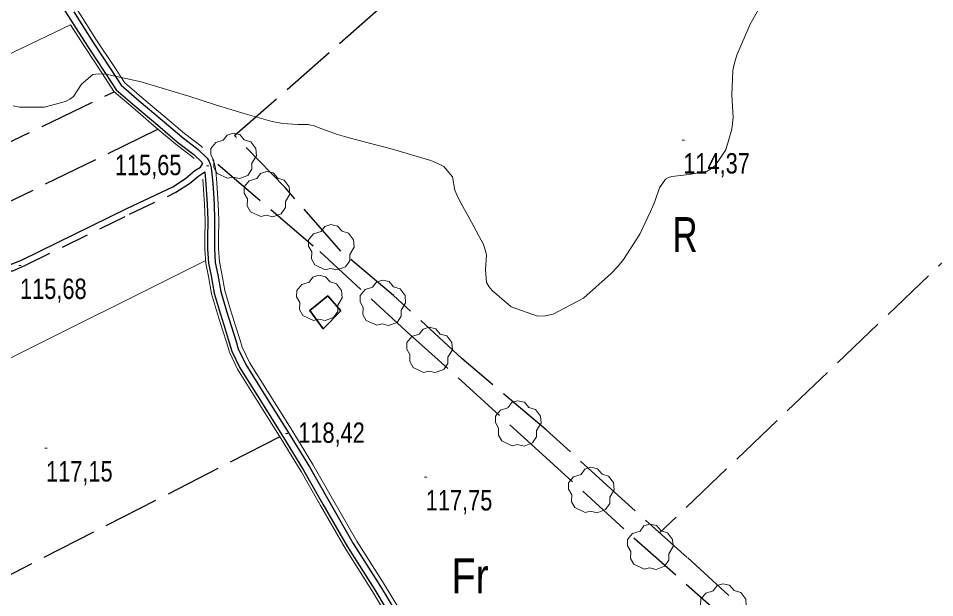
# Model space of a CAD drawing. Extents: x 487425 to 492029, y 4383576 to 4386788.
# Drawn here: x 489030 to 489424, y 4385743 to 4385991.9 of the extents above; entities that cross this region are included whole.
import ezdxf
from ezdxf.enums import TextEntityAlignment as Align

# ---------------------------------------------------------------- set-up
doc = ezdxf.new("R2010")
doc.units = 0
doc.header["$LTSCALE"] = 4
doc.linetypes.add('LONG_DASHED', pattern=[7.5, 6, -1.5])
doc.linetypes.add('MEDIUM_DASHED', pattern=[4.5, 3, -1.5])
for name, color, linetype, lineweight in [('25', 7, 'LONG_DASHED', 25), ('29', 7, 'Continuous', 13), ('38', 7, 'Continuous', 25), ('47', 7, 'Continuous', 35), ('51', 7, 'Continuous', 13), ('7', 7, 'Continuous', 13), ('9', 7, 'Continuous', 13)]:
    doc.layers.add(name, color=color, linetype=linetype, lineweight=lineweight)
doc.layers.add('31', color=7, linetype='Continuous')

msp = doc.modelspace()

# ---------------------------------------------------------------- linework, layer by layer
at = {"layer": '25'}
for p, q in [((488823.7, 4385841.92), (489071.21, 4385960.37)), ((489486.39, 4385943.41), (489305.75, 4385770.85))]:
    msp.add_line(p, q, dxfattribs=at)
for points in [[(489440.72, 4385647.8), (489419.55, 4385666.12), (489411.02, 4385668.4), (489411.06, 4385671.92), (489385.11, 4385699.07), (489357.64, 4385723.62), (489317.54, 4385760.31), (489289.47, 4385785.39), (489257.02, 4385815.16), (489220.69, 4385845.74), (489191.36, 4385872.85), (489168.69, 4385891.87), (489144.7, 4385919.22), (489122.97, 4385941.6), (489239.75, 4386043.95), (489321.93, 4386119.99), (489486.42, 4385943.37)], [(489090.11, 4385944.28), (488961.59, 4385881.69), (488988.3, 4385826.93)], [(489115.71, 4385929.31), (489159.69, 4385891.74), (489196.81, 4385857.49), (489250.5, 4385809.01), (489294.68, 4385768.67), (489335.01, 4385733.1), (489368.49, 4385701.89), (489404.14, 4385669.9), (489456.29, 4385624.52), (489481.26, 4385603.45)], [(489142.46, 4385812.11), (488991.66, 4385734.98), (489035.67, 4385658.64)]]:
    msp.add_lwpolyline(points, dxfattribs=at)
at = {"layer": '29'}
for points in [[(489119.97, 4385923.19), (489115.43, 4385925.31), (489114.02, 4385927.85), (489114.12, 4385930.83), (489112.75, 4385933.24), (489112.79, 4385935.99), (489114.95, 4385938.59), (489118.14, 4385939.59), (489119.79, 4385941.78), (489122.36, 4385942.61), (489125.22, 4385941.96), (489127.17, 4385939.69), (489129.98, 4385938.87), (489132.11, 4385936.02), (489132.35, 4385932.89), (489130.47, 4385929.74), (489130.47, 4385927.06), (489128.65, 4385924.45), (489125.03, 4385923.11), (489122.26, 4385923.74)], [(489134.33, 4385906.74), (489129.79, 4385908.86), (489128.38, 4385911.4), (489128.48, 4385914.38), (489127.11, 4385916.79), (489127.15, 4385919.54), (489129.31, 4385922.14), (489132.5, 4385923.14), (489134.15, 4385925.33), (489136.72, 4385926.16), (489139.58, 4385925.51), (489141.53, 4385923.24), (489144.34, 4385922.42), (489146.47, 4385919.57), (489146.71, 4385916.44), (489144.83, 4385913.29), (489144.83, 4385910.61), (489143.01, 4385908), (489139.39, 4385906.66), (489136.62, 4385907.29)], [(489161.98, 4385883.92), (489157.44, 4385886.04), (489156.03, 4385888.58), (489156.13, 4385891.56), (489154.76, 4385893.97), (489154.8, 4385896.72), (489156.96, 4385899.32), (489160.15, 4385900.32), (489161.8, 4385902.51), (489164.37, 4385903.34), (489167.23, 4385902.69), (489169.18, 4385900.42), (489171.99, 4385899.6), (489174.12, 4385896.75), (489174.36, 4385893.62), (489172.48, 4385890.47), (489172.48, 4385887.79), (489170.66, 4385885.18), (489167.04, 4385883.84), (489164.27, 4385884.47)], [(489156.86, 4385862.15), (489152.32, 4385864.27), (489150.91, 4385866.81), (489151.01, 4385869.79), (489149.64, 4385872.2), (489149.68, 4385874.95), (489151.84, 4385877.55), (489155.03, 4385878.55), (489156.68, 4385880.74), (489159.25, 4385881.57), (489162.11, 4385880.92), (489164.06, 4385878.65), (489166.87, 4385877.83), (489169, 4385874.98), (489169.24, 4385871.85), (489167.36, 4385868.7), (489167.36, 4385866.02), (489165.54, 4385863.41), (489161.92, 4385862.07), (489159.15, 4385862.7)], [(489184.14, 4385860.04), (489179.6, 4385862.16), (489178.19, 4385864.7), (489178.29, 4385867.68), (489176.92, 4385870.09), (489176.96, 4385872.84), (489179.12, 4385875.44), (489182.31, 4385876.44), (489183.96, 4385878.63), (489186.53, 4385879.46), (489189.39, 4385878.81), (489191.34, 4385876.54), (489194.15, 4385875.72), (489196.28, 4385872.87), (489196.52, 4385869.74), (489194.64, 4385866.59), (489194.64, 4385863.91), (489192.82, 4385861.3), (489189.2, 4385859.96), (489186.43, 4385860.59)], [(489204.24, 4385839.78), (489199.7, 4385841.9), (489198.29, 4385844.44), (489198.39, 4385847.42), (489197.02, 4385849.83), (489197.06, 4385852.58), (489199.22, 4385855.18), (489202.41, 4385856.18), (489204.06, 4385858.37), (489206.63, 4385859.2), (489209.49, 4385858.55), (489211.44, 4385856.28), (489214.25, 4385855.46), (489216.38, 4385852.61), (489216.62, 4385849.48), (489214.74, 4385846.33), (489214.74, 4385843.65), (489212.92, 4385841.04), (489209.3, 4385839.7), (489206.53, 4385840.33)], [(489242.37, 4385808.21), (489237.83, 4385810.33), (489236.42, 4385812.87), (489236.52, 4385815.85), (489235.15, 4385818.26), (489235.19, 4385821.01), (489237.35, 4385823.61), (489240.54, 4385824.61), (489242.19, 4385826.8), (489244.76, 4385827.63), (489247.62, 4385826.98), (489249.57, 4385824.71), (489252.38, 4385823.89), (489254.51, 4385821.04), (489254.75, 4385817.91), (489252.87, 4385814.76), (489252.87, 4385812.08), (489251.05, 4385809.47), (489247.43, 4385808.13), (489244.66, 4385808.76)], [(489273.78, 4385779.57), (489269.24, 4385781.69), (489267.83, 4385784.23), (489267.93, 4385787.21), (489266.56, 4385789.62), (489266.6, 4385792.37), (489268.76, 4385794.97), (489271.95, 4385795.97), (489273.6, 4385798.16), (489276.17, 4385798.99), (489279.03, 4385798.34), (489280.98, 4385796.07), (489283.79, 4385795.25), (489285.92, 4385792.4), (489286.16, 4385789.27), (489284.28, 4385786.12), (489284.28, 4385783.44), (489282.46, 4385780.83), (489278.84, 4385779.49), (489276.07, 4385780.12)], [(489299.16, 4385755.2), (489294.62, 4385757.32), (489293.21, 4385759.86), (489293.31, 4385762.84), (489291.94, 4385765.25), (489291.98, 4385768), (489294.14, 4385770.6), (489297.33, 4385771.6), (489298.98, 4385773.79), (489301.55, 4385774.62), (489304.41, 4385773.97), (489306.36, 4385771.7), (489309.17, 4385770.88), (489311.3, 4385768.03), (489311.54, 4385764.9), (489309.66, 4385761.75), (489309.66, 4385759.07), (489307.84, 4385756.46), (489304.22, 4385755.12), (489301.45, 4385755.75)], [(489330.6, 4385729.56), (489326.06, 4385731.68), (489324.65, 4385734.22), (489324.75, 4385737.2), (489323.38, 4385739.61), (489323.42, 4385742.36), (489325.58, 4385744.96), (489328.77, 4385745.96), (489330.42, 4385748.15), (489332.99, 4385748.98), (489335.85, 4385748.33), (489337.8, 4385746.06), (489340.61, 4385745.24), (489342.74, 4385742.39), (489342.98, 4385739.26), (489341.1, 4385736.11), (489341.1, 4385733.43), (489339.28, 4385730.82), (489335.66, 4385729.48), (489332.89, 4385730.11)]]:
    msp.add_lwpolyline(points, close=True, dxfattribs=at)
at = {"layer": '38'}
for points in [[(489042.28, 4386007.28), (489051.34, 4385993.15), (489059.68, 4385979.99), (489067.21, 4385968.71), (489072.01, 4385961.22), (489080.11, 4385954.34), (489089.92, 4385945.97), (489098.43, 4385938.79), (489105.44, 4385933.43), (489108.86, 4385930.08), (489109.24, 4385929.38)], [(489053.8, 4385994.72), (489062.13, 4385981.58), (489069.65, 4385970.31), (489074.23, 4385963.16), (489082, 4385956.56), (489091.81, 4385948.19), (489100.26, 4385941.07), (489107.36, 4385935.63), (489111.19, 4385931.87), (489112.03, 4385930.4), (489112.57, 4385928.8), (489112.88, 4385927.75), (489113.11, 4385926.38), (489113.57, 4385920.93), (489114.15, 4385912.19), (489114.37, 4385905.26), (489114.28, 4385897.37), (489114.31, 4385892.98), (489114.69, 4385887.06), (489115.74, 4385881.77), (489117.07, 4385874.52), (489119.51, 4385866.14), (489121.68, 4385859.3), (489123.49, 4385853.49), (489124.56, 4385849.94), (489127.8, 4385843.18), (489136.26, 4385829.62), (489146.5, 4385813.37), (489155.13, 4385799.23), (489163.51, 4385784.57), (489174.02, 4385766.31), (489185.74, 4385747.81), (489194.72, 4385732.92)], [(489016.31, 4385888.36), (489019.94, 4385886.53), (489023.86, 4385886.14), (489027.04, 4385886.24), (489031.64, 4385888.19), (489076.59, 4385910.25), (489096.45, 4385919.6), (489101.91, 4385923.13), (489105.94, 4385926.55), (489108.3, 4385928.01), (489109.24, 4385929.38)], [(489110.22, 4385925.95), (489110.66, 4385920.71), (489111.24, 4385912.05), (489111.46, 4385905.23), (489111.37, 4385897.37), (489111.4, 4385892.88), (489111.79, 4385886.68), (489112.87, 4385881.22), (489114.23, 4385873.84), (489116.73, 4385865.29), (489118.9, 4385858.42), (489120.71, 4385852.64), (489121.84, 4385848.89), (489125.24, 4385841.78), (489133.79, 4385828.08), (489144.02, 4385811.83), (489152.62, 4385797.75), (489160.99, 4385783.12), (489171.53, 4385764.8), (489183.26, 4385746.28), (489192.23, 4385731.42), (489204.59, 4385710.88), (489224.39, 4385677.11), (489231.34, 4385665.63)]]:
    msp.add_lwpolyline(points, dxfattribs=at)
at = {"layer": '38', "linetype": 'MEDIUM_DASHED'}
msp.add_lwpolyline([(489015.07, 4385885.9), (489019.16, 4385883.84), (489023.76, 4385883.38), (489027.64, 4385883.5), (489032.79, 4385885.68), (489077.79, 4385907.76), (489097.79, 4385917.19), (489103.56, 4385920.91), (489107.57, 4385924.31), (489110.22, 4385925.95)], dxfattribs=at)
at = {"layer": '47'}
msp.add_lwpolyline([(489168.63, 4385866.28), (489161.11, 4385858.49), (489155.28, 4385866.44), (489163.07, 4385872.65)], close=True, dxfattribs=at)
at = {"layer": '51'}
for p, q in [((488805.88, 4385871.46), (489052.49, 4385989.15)), ((489110.55, 4385887.85), (488868.95, 4385767.45))]:
    msp.add_line(p, q, dxfattribs=at)
for points in [[(489046.25, 4386009.83), (489055.33, 4385995.7), (489063.65, 4385982.57), (489071.17, 4385971.3), (489075.61, 4385964.36), (489083.17, 4385957.94), (489092.98, 4385949.58), (489101.4, 4385942.49), (489108.55, 4385937), (489109.2, 4385936.38)], [(489105.59, 4385931.65), (489104.67, 4385932.54), (489097.69, 4385937.87), (489089.16, 4385945.07), (489079.35, 4385953.45), (489071.12, 4385960.44), (489066.23, 4385968.07), (489058.7, 4385979.35), (489052.49, 4385989.15)], [(489196.27, 4385733.85), (489187.28, 4385748.77), (489175.57, 4385767.25), (489165.09, 4385785.48), (489156.69, 4385800.15), (489148.04, 4385814.33), (489137.8, 4385830.58), (489129.39, 4385844.06), (489126.25, 4385850.6), (489125.23, 4385854.02), (489123.41, 4385859.85), (489121.25, 4385866.66), (489118.83, 4385874.93), (489117.52, 4385882.11), (489116.49, 4385887.29), (489116.13, 4385893.05), (489116.1, 4385897.36), (489116.19, 4385905.28), (489115.96, 4385912.28), (489115.38, 4385921.07), (489114.91, 4385926.61), (489114.65, 4385928.16), (489114.3, 4385929.35), (489113.69, 4385931.14), (489113.56, 4385931.39)], [(489229.57, 4385666.3), (489223.38, 4385676.51), (489203.58, 4385710.28), (489191.22, 4385730.81), (489182.26, 4385745.66), (489170.52, 4385764.19), (489159.97, 4385782.54), (489151.61, 4385797.15), (489143.02, 4385811.21), (489132.79, 4385827.46), (489124.21, 4385841.21), (489120.74, 4385848.46), (489119.59, 4385852.3), (489117.78, 4385858.07), (489115.61, 4385864.95), (489113.09, 4385873.57), (489111.72, 4385881), (489110.62, 4385886.53), (489110.23, 4385892.84), (489110.2, 4385897.37), (489110.29, 4385905.22), (489110.07, 4385911.99), (489109.49, 4385920.62), (489109.31, 4385922.77)]]:
    msp.add_lwpolyline(points, dxfattribs=at)
at = {"layer": '7'}
for p, q in [((489315.41, 4385939.63), (489316.41, 4385939.63)), ((489110.84, 4385928.53), (489111.84, 4385928.53)), ((489030.23, 4385885.71), (489031.23, 4385885.71)), ((489144.87, 4385813.51), (489145.87, 4385813.51)), ((489041.42, 4385807.26), (489042.42, 4385807.26)), ((489204.68, 4385794.82), (489205.68, 4385794.82))]:
    msp.add_line(p, q, dxfattribs=at)
at = {"layer": '9'}
for points in [[(489053.76, 4385958.29), (489057.16, 4385963.7), (489062.03, 4385967.74), (489064.56, 4385968.03), (489067.6, 4385967.96), (489082.85, 4385964.71), (489097.96, 4385960.14), (489100.93, 4385959.23), (489103.36, 4385958.48), (489107.72, 4385957.08), (489111.15, 4385955.93), (489113, 4385955.34), (489115.24, 4385954.64), (489126.54, 4385951.13), (489138.58, 4385947.79), (489141.28, 4385947.19), (489143.7, 4385946.73), (489150.16, 4385946.26), (489154.57, 4385946.26), (489155.71, 4385946.1), (489156.81, 4385945.88), (489160.45, 4385944.48), (489167.19, 4385942.02), (489170.24, 4385941.12), (489173.8, 4385940.13), (489190.92, 4385935.76), (489207.32, 4385930.88), (489210.42, 4385929.57), (489212.9, 4385928.28), (489216.65, 4385923.76), (489217.72, 4385918.11), (489218.51, 4385916.1), (489219.51, 4385913.9), (489224.91, 4385904.36), (489229.96, 4385894.68), (489230.74, 4385892.39), (489231.25, 4385890.27), (489230.88, 4385884.03), (489231.28, 4385878.43), (489232.29, 4385876.72), (489233.68, 4385874.94), (489241.94, 4385867.93), (489253.26, 4385863.97), (489256.59, 4385864.12), (489260, 4385864.8), (489273.01, 4385871.75), (489284.97, 4385882.32), (489287.73, 4385885.28), (489290.23, 4385888.26), (489297.26, 4385899.16), (489301.85, 4385908.91), (489302.83, 4385911.17), (489303.67, 4385913.24), (489305.64, 4385919.11), (489308.29, 4385922.79), (489309.56, 4385923.48), (489311.06, 4385924.02), (489318.4, 4385924.79), (489326.22, 4385926.32), (489328.01, 4385927.35), (489329.65, 4385928.64), (489334.21, 4385935.49), (489336.76, 4385944.29), (489337.12, 4385946.81), (489337.33, 4385949.37), (489336.86, 4385958.91), (489337.18, 4385969.53), (489337.89, 4385972.77), (489338.88, 4385976.14), (489344.7, 4385989.38), (489351.24, 4386001.18)], [(489027.82, 4385954.29), (489030.53, 4385953.79), (489041.05, 4385953.78), (489050.26, 4385956.14), (489052.15, 4385957.14), (489053.76, 4385958.29)]]:
    msp.add_lwpolyline(points, dxfattribs=at)

# ---------------------------------------------------------------- texts
at = {"layer": '31'}
for s, width, p in [('R', 0.75, (489316.66, 4385891.53)), ('Fr', 0.85, (489224.23, 4385744.82))]:
    msp.add_text(s, height=15, dxfattribs=dict(at, width=width)).set_placement(p, align=Align.CENTER)
at = {"layer": '7', "width": 0.8}
for s, p in [('115,65', (489071.5, 4385924.54)), ('114,37', (489315.91, 4385925.26)), ('115,68', (489030.73, 4385871.34)), ('118,42', (489150.35, 4385809.52)), ('117,15', (489041.92, 4385792.89)), ('117,75', (489205.18, 4385780.45))]:
    msp.add_text(s, height=8.75, dxfattribs=at).set_placement(p)

doc.saveas('drawing.dxf')
